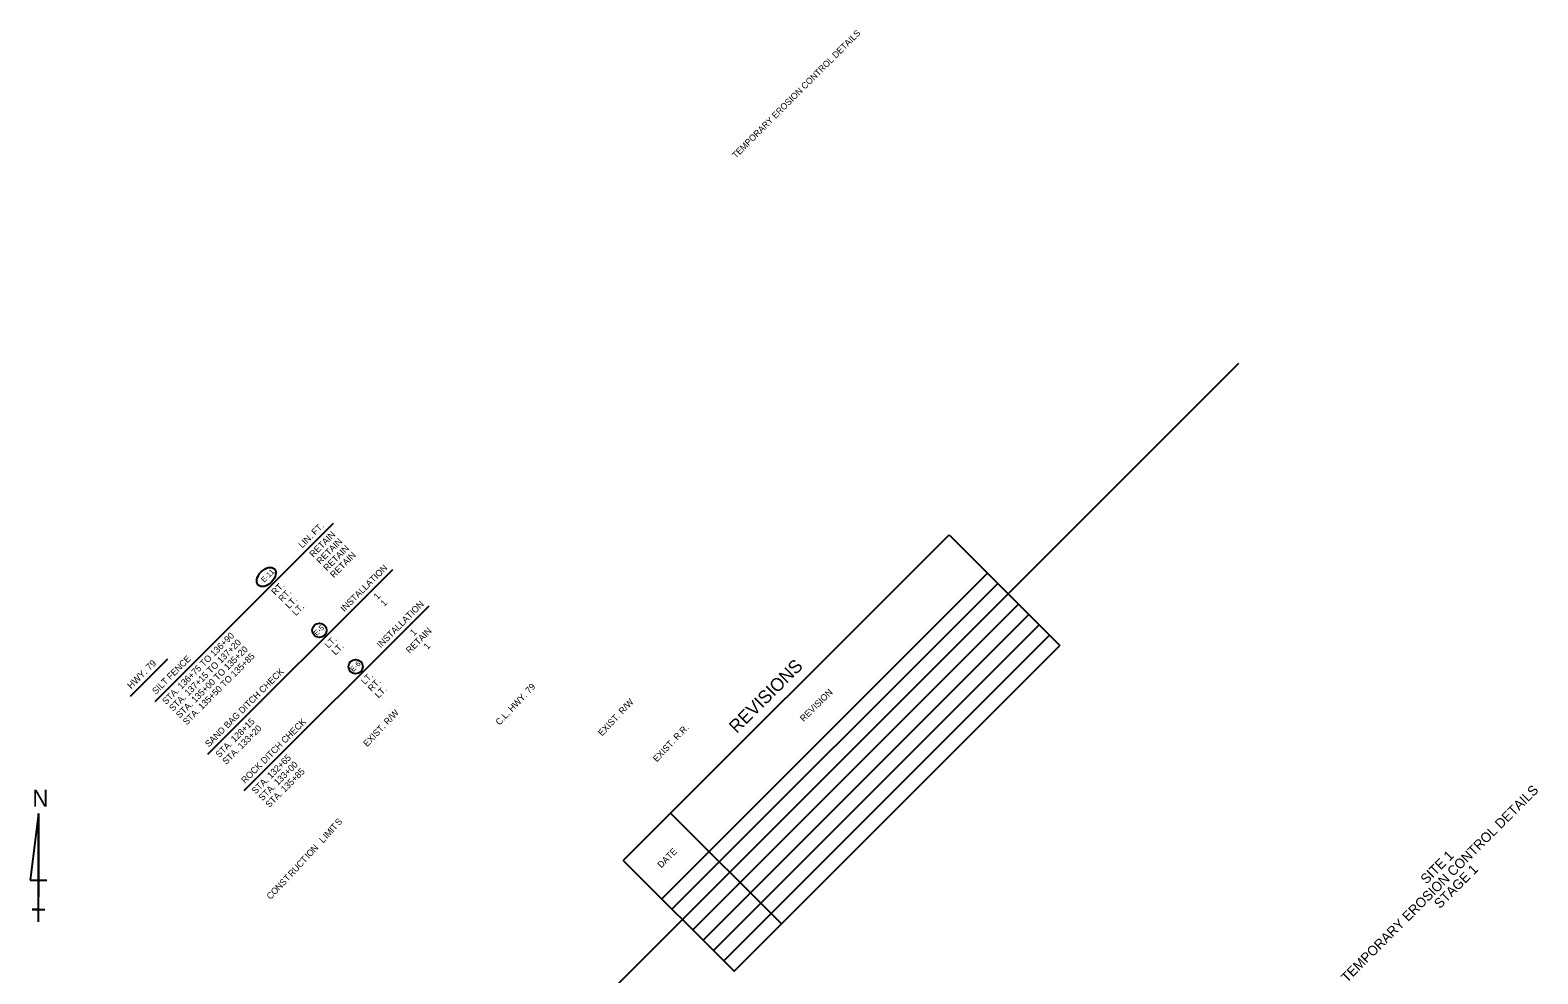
# Model space of a CAD drawing. Extents: x 1377476 to 1378879, y 1932630 to 1934097.
# Drawn here: x 1377489 to 1378879, y 1933226 to 1934097 of the extents above; entities that cross this region are included whole.
import ezdxf

# ---------------------------------------------------------------- set-up
doc = ezdxf.new("R2010")
doc.units = 0
for name, color, linetype in [('1', 7, 'Continuous'), ('44', 7, 'Continuous'), ('60', 7, 'Continuous'), ('63', 7, 'Continuous'), ('Default', 7, 'Continuous'), ('R_Draft', 7, 'Continuous')]:
    doc.layers.add(name, color=color, linetype=linetype)

msp = doc.modelspace()

# ---------------------------------------------------------------- linework, layer by layer
at = {"layer": '1'}
for p, q in [((1378390.8, 1933576.6), (1378603.6, 1933789.5)), ((1377887.9, 1933073.8), (1378090.3, 1933276.1))]:
    msp.add_line(p, q, dxfattribs=at)
for centre in [(1377755.5, 1933543), (1377788.9, 1933509.5)]:
    msp.add_circle(centre, 6.61, dxfattribs=at)
msp.add_ellipse((1377706.5, 1933592.2), major_axis=(7.44, 7.44), ratio=0.638788, dxfattribs=at)
at = {"layer": '44'}
for p, q in [((1377604, 1933477.4), (1377768.6, 1933642)), ((1377652.7, 1933428.6), (1377823.2, 1933599)), ((1377686.2, 1933395.2), (1377856.6, 1933565.6)), ((1377581.2, 1933482.3), (1377615.7, 1933516.8))]:
    msp.add_line(p, q, dxfattribs=at)
at = {"layer": '63'}
for p, q in [((1377496.3, 1933374), (1377488.7, 1933312.5)), ((1377496.3, 1933274), (1377496.3, 1933374)), ((1377496.3, 1933374), (1377496.3, 1933297.1)), ((1377488.7, 1933312.5), (1377504, 1933312.5)), ((1377496.3, 1933274), (1377496.3, 1933297.1)), ((1377496.3, 1933285.5), (1377490.6, 1933285.5)), ((1377490.6, 1933285.5), (1377502.1, 1933285.5)), ((1377496.3, 1933274), (1377496.3, 1933285.5))]:
    msp.add_line(p, q, dxfattribs=at)
at = {"layer": 'Default'}
for p, q in [((1378035.8, 1933330.6), (1378336.3, 1933631.1)), ((1378336.3, 1933631.1), (1378438.5, 1933528.9)), ((1378071.2, 1933295.2), (1378371.7, 1933595.7)), ((1378080.7, 1933285.7), (1378381.2, 1933586.2)), ((1378090.3, 1933276.1), (1378390.8, 1933576.6)), ((1378099.8, 1933266.6), (1378400.3, 1933567.1)), ((1378099.8, 1933266.6), (1378400.3, 1933567.1)), ((1378109.4, 1933257), (1378409.9, 1933557.5)), ((1378118.9, 1933247.5), (1378419.4, 1933548)), ((1378128.5, 1933237.9), (1378429, 1933538.5)), ((1378138, 1933228.4), (1378438.5, 1933528.9)), ((1378079.5, 1933374.3), (1378181.7, 1933272.1)), ((1378035.8, 1933330.6), (1378138, 1933228.4))]:
    msp.add_line(p, q, dxfattribs=at)

# ---------------------------------------------------------------- texts
at = {"layer": '1'}
for s, height, p in [('TEMPORARY EROSION CONTROL DETAILS', 5.862, (1378139.6, 1933978.1)), ('E-11', 4.8, (1377704.5, 1933586.8)), ('E-5 ', 4.8, (1377753, 1933537.6)), ('E-6 ', 4.8, (1377786.7, 1933504.4))]:
    msp.add_text(s, height=height, rotation=45, dxfattribs=at).set_placement(p)
at = {"layer": '44'}
for s, height, p in [('LIN. FT.', 6, (1377739.7, 1933618.4)), ('RETAIN', 6, (1377749.9, 1933610)), ('RETAIN', 6, (1377756.3, 1933603.6)), ('RETAIN', 6, (1377762.6, 1933597.3)), ('RETAIN', 6, (1377768.9, 1933591)), ('INSTALLATION', 6, (1377778.5, 1933559.7)), ('RT.', 6, (1377714.7, 1933575)), ('RT.', 6, (1377721.1, 1933568.7)), ('1', 6, (1377809.1, 1933570.9)), ('LT.', 6, (1377727.5, 1933562.5)), ('LT.', 6, (1377733.8, 1933556.1)), ('INSTALLATION', 6, (1377812, 1933526.3)), ('1', 6, (1377815.4, 1933564.6)), ('STA. 136+75 TO 136+90', 6, (1377614, 1933474.1)), ('STA. 137+15 TO 137+20', 6, (1377620.4, 1933467.8)), ('LT.', 6, (1377763.9, 1933526)), ('RETAIN', 6, (1377838.8, 1933521.1)), ('1', 6, (1377842.6, 1933537.5)), ('SILT FENCE      ', 6, (1377604.7, 1933483.4)), ('STA. 135+00 TO 135+20', 6, (1377626.7, 1933461.5)), ('STA. 135+50 TO 135+85', 6, (1377633, 1933455.1)), ('LT.', 6, (1377770.3, 1933519.7)), ('1', 6, (1377855.2, 1933524.8)), ('HWY. 79', 6.25, (1377581.9, 1933488.4)), ('SAND BAG DITCH CHECK', 6, (1377653.5, 1933434.7)), ('LT.', 6, (1377797.4, 1933492.5)), ('RT.', 6, (1377803.6, 1933486.1)), ('LT.', 6, (1377810.1, 1933479.9)), ('STA. 128+15', 6, (1377663.1, 1933425)), ('STA. 133+20', 6, (1377669.5, 1933418.7)), ('ROCK DITCH CHECK', 6, (1377686.9, 1933401.2)), ('STA. 132+65', 6, (1377696.6, 1933391.5)), ('STA. 133+00', 6, (1377702.9, 1933385.2)), ('STA. 135+85', 6, (1377709.3, 1933378.9))]:
    msp.add_text(s, height=height, rotation=45, dxfattribs=at).set_placement(p)
at = {"layer": '60'}
for s, p in [('TEMPORARY EROSION CONTROL DETAILS', (1378703.4, 1933217.4)), ('SITE 1', (1378776.6, 1933308.2)), ('STAGE 1', (1378789.1, 1933285.6))]:
    msp.add_text(s, height=9, rotation=45, dxfattribs=at).set_placement(p)
at = {"layer": '63'}
msp.add_text('N', height=15.4, rotation=360, dxfattribs=at).set_placement((1377490.7, 1933380.4))
at = {"layer": 'Default'}
for s, height, p in [('REVISIONS', 12, (1378140.5, 1933447.2)), ('REVISION', 6, (1378202.3, 1933458.2)), ('DATE', 6, (1378070.9, 1933323.2))]:
    msp.add_text(s, height=height, rotation=45, dxfattribs=at).set_placement(p)
at = {"layer": 'R_Draft'}
for s, rotation, p in [('C.L. HWY. 79', 46.6607, (1377921.6, 1933454.9)), ('EXIST. R/W', 46.6607, (1378016.2, 1933444.9)), ('EXIST. R/W', 46.6607, (1377799.6, 1933435.1)), ('EXIST. R.R.', 46.6607, (1378066.8, 1933421)), ('T', 47.8304, (1377769.6, 1933357.9)), ('S', 47.6982, (1377773.5, 1933362.2)), ('L', 47.3329, (1377759, 1933346.2)), ('I', 47.6504, (1377762.6, 1933350.2)), ('M', 47.6504, (1377764, 1933351.7)), ('I', 47.8304, (1377768.3, 1933356.4)), ('O', 47.0787, (1377747.1, 1933333.4)), ('N', 47.0787, (1377751.1, 1933337.7)), ('U', 47.1581, (1377734, 1933319.2)), ('C', 47.1581, (1377737.9, 1933323.4)), ('T', 47.5667, (1377741.8, 1933327.6)), ('I', 47.0787, (1377745.7, 1933331.9)), ('N', 46.2518, (1377718.3, 1933302.5)), ('S', 46.2518, (1377722.3, 1933306.6)), ('T', 47.3987, (1377726.2, 1933310.7)), ('R', 47.3987, (1377730.2, 1933315)), ('C', 47.835, (1377710.5, 1933294.1)), ('O', 46.6191, (1377714.3, 1933298.3))]:
    msp.add_text(s, height=6, rotation=rotation, dxfattribs=at).set_placement(p)

doc.saveas('drawing.dxf')
